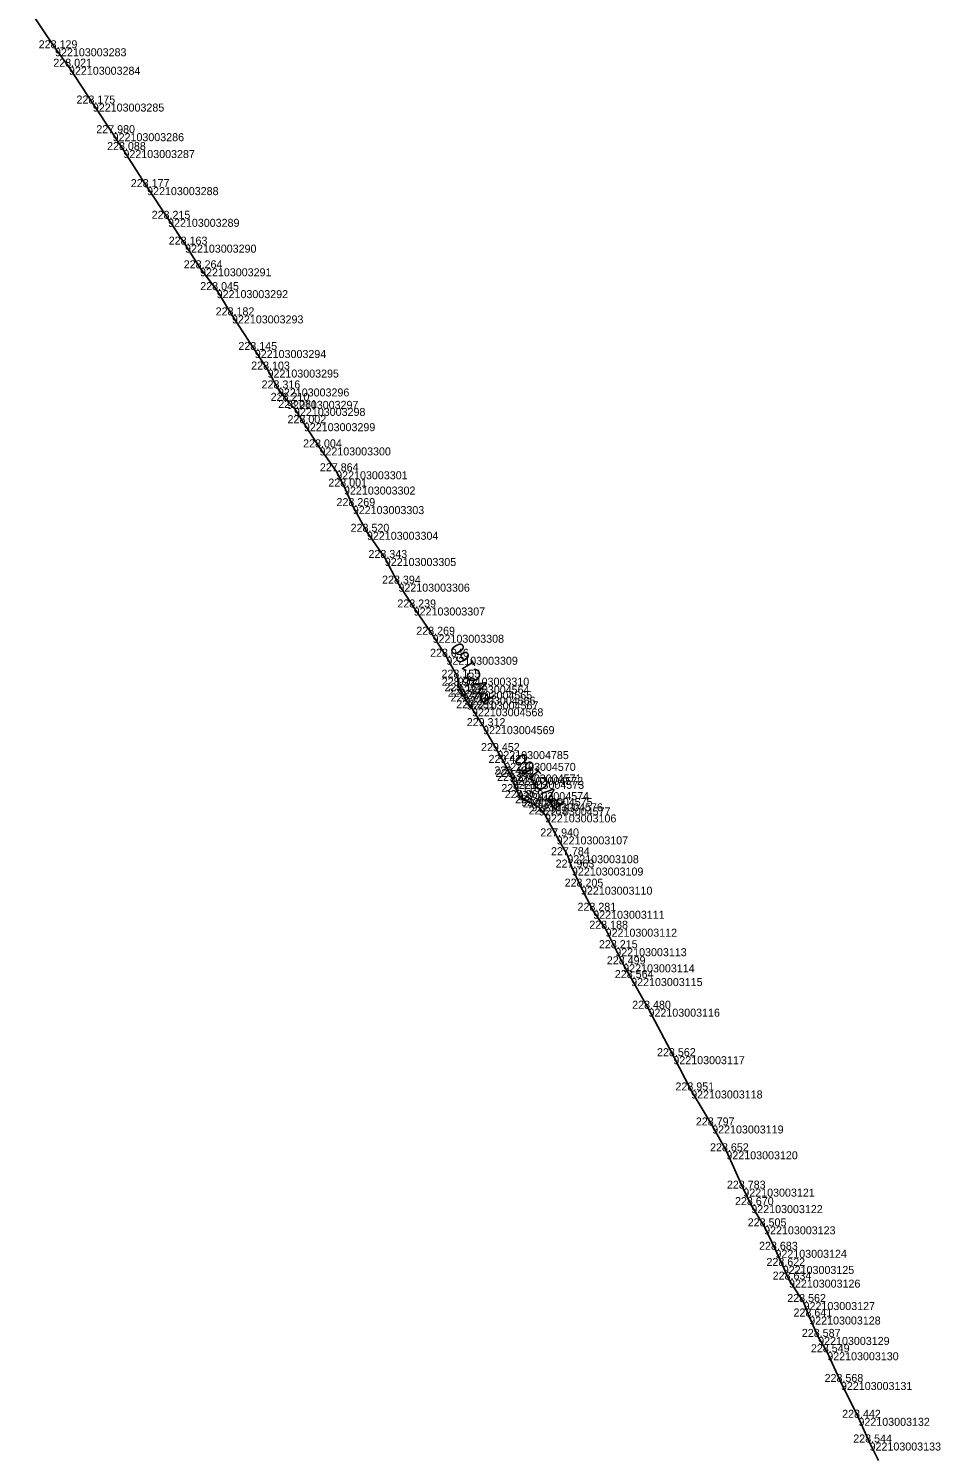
# Model space of a CAD drawing. Extents: x -771047 to -756200, y -1053876 to -1046520.
# Drawn here: x -769310.8 to -769174, y -1050962.3 to -1050749 of the extents above; entities that cross this region are included whole.
import ezdxf

# ---------------------------------------------------------------- set-up
doc = ezdxf.new("R2010")
doc.units = 0
for name, color, linetype in [('Vrstva 32', 7, 'Continuous'), ('Vrstva 33', 7, 'Continuous'), ('Vrstva 60', 7, 'Continuous'), ('Vrstva 61', 7, 'Continuous')]:
    doc.layers.add(name, color=color, linetype=linetype)

msp = doc.modelspace()

# ---------------------------------------------------------------- linework, layer by layer
at = {"layer": 'Vrstva 32'}
for points in [[(-769310.84, -1050745.98), (-769306.85, -1050751.92), (-769304.76, -1050754.69), (-769301.18, -1050760.21), (-769298.21, -1050764.65), (-769296.59, -1050767.18), (-769293.04, -1050772.74), (-769289.9, -1050777.49), (-769287.35, -1050781.36), (-769285.1, -1050784.91), (-769282.61, -1050788.18), (-769280.31, -1050791.97), (-769276.89, -1050797.16), (-769274.98, -1050800.09), (-769273.42, -1050802.92), (-769272.06, -1050804.78), (-769271.01, -1050805.84), (-769269.53, -1050808.13), (-769267.19, -1050811.76), (-769264.68, -1050815.34), (-769263.51, -1050817.63), (-769262.19, -1050820.56), (-769260.07, -1050824.41), (-769257.39, -1050828.34), (-769255.35, -1050832.19), (-769253.06, -1050835.76), (-769250.22, -1050839.85), (-769248.15, -1050843.15), (-769246.44, -1050846.28)], [(-769246.44, -1050846.28), (-769246.4, -1050847.49), (-769246, -1050848.32), (-769245.49, -1050849.14)], [(-769245.49, -1050849.14), (-769245.07, -1050849.85), (-769244.32, -1050850.87), (-769242.65, -1050853.55), (-769240.51, -1050857.29), (-769239.47, -1050859.06), (-769238.61, -1050860.79), (-769238.35, -1050861.17)], [(-769238.35, -1050861.17), (-769238.2, -1050861.75), (-769237.47, -1050863.44), (-769236.94, -1050864.34), (-769235.39, -1050865.11), (-769234.25, -1050865.74), (-769233.37, -1050866.78)], [(-769233.37, -1050866.78), (-769231.61, -1050870.08), (-769230.01, -1050872.9), (-769229.32, -1050874.75), (-769227.97, -1050877.62), (-769226.13, -1050881.23), (-769224.27, -1050883.92), (-769222.82, -1050886.84), (-769221.63, -1050889.26), (-769220.44, -1050891.32), (-769217.84, -1050895.92), (-769214.11, -1050903.03), (-769211.44, -1050908.17), (-769208.29, -1050913.42), (-769206.16, -1050917.29), (-769203.62, -1050922.89), (-769202.42, -1050925.36), (-769200.5, -1050928.54), (-769198.8, -1050932.06), (-769197.7, -1050934.48), (-769196.77, -1050936.53), (-769194.58, -1050939.89), (-769193.73, -1050942.06), (-769192.39, -1050945.12), (-769191.03, -1050947.42), (-769188.98, -1050951.88), (-769186.35, -1050957.25), (-769184.68, -1050960.95), (-769183.32, -1050963.66)]]:
    msp.add_lwpolyline(points, dxfattribs=at)
at = {"layer": 'Vrstva 33'}
for points in [[(-769246.44, -1050846.28), (-769246.4, -1050847.49), (-769246, -1050848.32), (-769245.49, -1050849.14)], [(-769238.35, -1050861.17), (-769238.2, -1050861.75), (-769237.47, -1050863.44), (-769236.94, -1050864.34), (-769235.39, -1050865.11), (-769234.25, -1050865.74), (-769233.37, -1050866.78)]]:
    msp.add_lwpolyline(points, dxfattribs=at)
at = {"layer": 'Vrstva 60'}
for p, q in [((-769306.85, -1050751.92), (-769306.85, -1050751.92)), ((-769304.76, -1050754.69), (-769304.76, -1050754.69)), ((-769301.18, -1050760.21), (-769301.18, -1050760.21)), ((-769298.21, -1050764.65), (-769298.21, -1050764.65)), ((-769296.59, -1050767.18), (-769296.59, -1050767.18)), ((-769293.04, -1050772.74), (-769293.04, -1050772.74)), ((-769289.9, -1050777.49), (-769289.9, -1050777.49)), ((-769287.35, -1050781.36), (-769287.35, -1050781.36)), ((-769285.1, -1050784.91), (-769285.1, -1050784.91)), ((-769282.61, -1050788.18), (-769282.61, -1050788.18)), ((-769280.31, -1050791.97), (-769280.31, -1050791.97)), ((-769276.89, -1050797.16), (-769276.89, -1050797.16)), ((-769274.98, -1050800.09), (-769274.98, -1050800.09)), ((-769273.42, -1050802.92), (-769273.42, -1050802.92)), ((-769272.06, -1050804.78), (-769272.06, -1050804.78)), ((-769271.01, -1050805.84), (-769271.01, -1050805.84)), ((-769269.53, -1050808.13), (-769269.53, -1050808.13)), ((-769267.19, -1050811.76), (-769267.19, -1050811.76)), ((-769264.68, -1050815.34), (-769264.68, -1050815.34)), ((-769263.51, -1050817.63), (-769263.51, -1050817.63)), ((-769262.19, -1050820.56), (-769262.19, -1050820.56)), ((-769260.07, -1050824.41), (-769260.07, -1050824.41)), ((-769257.39, -1050828.34), (-769257.39, -1050828.34)), ((-769255.35, -1050832.19), (-769255.35, -1050832.19)), ((-769253.06, -1050835.76), (-769253.06, -1050835.76)), ((-769250.22, -1050839.85), (-769250.22, -1050839.85)), ((-769248.15, -1050843.15), (-769248.15, -1050843.15)), ((-769246.44, -1050846.28), (-769246.44, -1050846.28)), ((-769246.4, -1050847.49), (-769246.4, -1050847.49)), ((-769246, -1050848.32), (-769246, -1050848.32)), ((-769245.49, -1050849.14), (-769245.49, -1050849.14)), ((-769245.07, -1050849.85), (-769245.07, -1050849.85)), ((-769244.32, -1050850.87), (-769244.32, -1050850.87)), ((-769242.65, -1050853.55), (-769242.65, -1050853.55)), ((-769240.51, -1050857.29), (-769240.51, -1050857.29)), ((-769239.47, -1050859.06), (-769239.47, -1050859.06)), ((-769238.61, -1050860.79), (-769238.61, -1050860.79)), ((-769238.35, -1050861.17), (-769238.35, -1050861.17)), ((-769238.2, -1050861.75), (-769238.2, -1050861.75)), ((-769237.47, -1050863.44), (-769237.47, -1050863.44)), ((-769236.94, -1050864.34), (-769236.94, -1050864.34)), ((-769235.39, -1050865.11), (-769235.39, -1050865.11)), ((-769234.25, -1050865.74), (-769234.25, -1050865.74)), ((-769233.37, -1050866.78), (-769233.37, -1050866.78)), ((-769231.61, -1050870.08), (-769231.61, -1050870.08)), ((-769230.01, -1050872.9), (-769230.01, -1050872.9)), ((-769229.32, -1050874.75), (-769229.32, -1050874.75)), ((-769227.97, -1050877.62), (-769227.97, -1050877.62)), ((-769226.13, -1050881.23), (-769226.13, -1050881.23)), ((-769224.27, -1050883.92), (-769224.27, -1050883.92)), ((-769222.82, -1050886.84), (-769222.82, -1050886.84)), ((-769221.63, -1050889.26), (-769221.63, -1050889.26)), ((-769220.44, -1050891.32), (-769220.44, -1050891.32)), ((-769217.84, -1050895.92), (-769217.84, -1050895.92)), ((-769214.11, -1050903.03), (-769214.11, -1050903.03)), ((-769211.44, -1050908.17), (-769211.44, -1050908.17)), ((-769208.29, -1050913.42), (-769208.29, -1050913.42)), ((-769206.16, -1050917.29), (-769206.16, -1050917.29)), ((-769203.62, -1050922.89), (-769203.62, -1050922.89)), ((-769202.42, -1050925.36), (-769202.42, -1050925.36)), ((-769200.5, -1050928.54), (-769200.5, -1050928.54)), ((-769198.8, -1050932.06), (-769198.8, -1050932.06)), ((-769197.7, -1050934.48), (-769197.7, -1050934.48)), ((-769196.77, -1050936.53), (-769196.77, -1050936.53)), ((-769194.58, -1050939.89), (-769194.58, -1050939.89)), ((-769193.73, -1050942.06), (-769193.73, -1050942.06)), ((-769192.39, -1050945.12), (-769192.39, -1050945.12)), ((-769191.03, -1050947.42), (-769191.03, -1050947.42)), ((-769188.98, -1050951.88), (-769188.98, -1050951.88)), ((-769186.35, -1050957.25), (-769186.35, -1050957.25)), ((-769184.68, -1050960.95), (-769184.68, -1050960.95))]:
    msp.add_line(p, q, dxfattribs=at)

# ---------------------------------------------------------------- texts
at = {"layer": 'Vrstva 33'}
for rotation, p in [(121.4913, (-769240.81, -1050849.29)), (129.9401, (-769230.24, -1050865.02))]:
    msp.add_text('PVC160', height=2, rotation=rotation, dxfattribs=at).set_placement(p)
at = {"layer": 'Vrstva 60'}
for s, p in [('922103003283', (-769306.85, -1050753.12)), ('922103003284', (-769304.76, -1050755.89)), ('922103003285', (-769301.18, -1050761.41)), ('922103003286', (-769298.21, -1050765.85)), ('922103003287', (-769296.59, -1050768.38)), ('922103003288', (-769293.04, -1050773.94)), ('922103003289', (-769289.9, -1050778.69)), ('922103003290', (-769287.35, -1050782.56)), ('922103003291', (-769285.1, -1050786.11)), ('922103003292', (-769282.61, -1050789.38)), ('922103003293', (-769280.31, -1050793.17)), ('922103003294', (-769276.89, -1050798.36)), ('922103003295', (-769274.98, -1050801.29)), ('922103003296', (-769273.42, -1050804.12)), ('922103003297', (-769272.06, -1050805.98)), ('922103003298', (-769271.01, -1050807.04)), ('922103003299', (-769269.53, -1050809.33)), ('922103003300', (-769267.19, -1050812.96)), ('922103003301', (-769264.68, -1050816.54)), ('922103003302', (-769263.51, -1050818.83)), ('922103003303', (-769262.19, -1050821.76)), ('922103003304', (-769260.07, -1050825.61)), ('922103003305', (-769257.39, -1050829.54)), ('922103003306', (-769255.35, -1050833.39)), ('922103003307', (-769253.06, -1050836.96)), ('922103003308', (-769250.22, -1050841.05)), ('922103003309', (-769248.15, -1050844.35)), ('922103003310', (-769246.44, -1050847.48)), ('922103004564', (-769246.4, -1050848.69)), ('922103004565', (-769246, -1050849.52)), ('922103004566', (-769245.49, -1050850.34)), ('922103004567', (-769245.07, -1050851.05)), ('922103004568', (-769244.32, -1050852.07)), ('922103004569', (-769242.65, -1050854.75)), ('922103004785', (-769240.51, -1050858.49)), ('922103004570', (-769239.47, -1050860.26)), ('922103004571', (-769238.61, -1050861.99)), ('922103004572', (-769238.35, -1050862.37)), ('922103004573', (-769238.2, -1050862.95)), ('922103004574', (-769237.47, -1050864.64)), ('922103004575', (-769236.94, -1050865.54)), ('922103004576', (-769235.39, -1050866.31)), ('922103004577', (-769234.25, -1050866.94)), ('922103003106', (-769233.37, -1050867.98)), ('922103003107', (-769231.61, -1050871.28)), ('922103003108', (-769230.01, -1050874.1)), ('922103003109', (-769229.32, -1050875.95)), ('922103003110', (-769227.97, -1050878.82)), ('922103003111', (-769226.13, -1050882.43)), ('922103003112', (-769224.27, -1050885.12)), ('922103003113', (-769222.82, -1050888.04)), ('922103003114', (-769221.63, -1050890.46)), ('922103003115', (-769220.44, -1050892.52)), ('922103003116', (-769217.84, -1050897.11)), ('922103003117', (-769214.11, -1050904.23)), ('922103003118', (-769211.44, -1050909.37)), ('922103003119', (-769208.29, -1050914.62)), ('922103003120', (-769206.16, -1050918.49)), ('922103003121', (-769203.62, -1050924.09)), ('922103003122', (-769202.42, -1050926.56)), ('922103003123', (-769200.5, -1050929.74)), ('922103003124', (-769198.8, -1050933.26)), ('922103003125', (-769197.7, -1050935.68)), ('922103003126', (-769196.77, -1050937.73)), ('922103003127', (-769194.58, -1050941.09)), ('922103003128', (-769193.73, -1050943.26)), ('922103003129', (-769192.39, -1050946.32)), ('922103003130', (-769191.03, -1050948.62)), ('922103003131', (-769188.98, -1050953.08)), ('922103003132', (-769186.35, -1050958.45)), ('922103003133', (-769184.68, -1050962.15))]:
    msp.add_text(s, height=1.2, dxfattribs=at).set_placement(p)
at = {"layer": 'Vrstva 61'}
for s, p in [('228.129', (-769309.3, -1050751.92)), ('228.021', (-769307.11, -1050754.69)), ('228.175', (-769303.63, -1050760.21)), ('227.980', (-769300.66, -1050764.65)), ('228.088', (-769299.04, -1050767.18)), ('228.177', (-769295.49, -1050772.74)), ('228.215', (-769292.36, -1050777.49)), ('228.163', (-769289.8, -1050781.36)), ('228.264', (-769287.55, -1050784.91)), ('228.045', (-769285.07, -1050788.18)), ('228.182', (-769282.76, -1050791.97)), ('228.145', (-769279.35, -1050797.16)), ('228.103', (-769277.43, -1050800.09)), ('228.316', (-769275.87, -1050802.92)), ('228.210', (-769274.51, -1050804.78)), ('228.081', (-769273.37, -1050805.84)), ('228.002', (-769271.98, -1050808.13)), ('228.004', (-769269.64, -1050811.76)), ('227.864', (-769267.13, -1050815.34)), ('228.001', (-769265.86, -1050817.63)), ('228.269', (-769264.64, -1050820.56)), ('228.520', (-769262.52, -1050824.41)), ('228.343', (-769259.84, -1050828.34)), ('228.394', (-769257.8, -1050832.19)), ('228.239', (-769255.51, -1050835.76)), ('228.269', (-769252.67, -1050839.85)), ('228.046', (-769250.6, -1050843.15)), ('228.155', (-769248.89, -1050846.28)), ('228.904', (-769248.85, -1050847.49)), ('229.167', (-769248.45, -1050848.32)), ('229.297', (-769247.94, -1050849.14)), ('229.274', (-769247.52, -1050849.85)), ('229.251', (-769246.68, -1050850.87)), ('229.312', (-769245.1, -1050853.55)), ('229.452', (-769242.96, -1050857.29)), ('229.421', (-769241.83, -1050859.06)), ('229.401', (-769240.96, -1050860.79)), ('229.392', (-769240.8, -1050861.17)), ('229.271', (-769240.55, -1050861.75)), ('229.116', (-769239.92, -1050863.44)), ('228.869', (-769239.4, -1050864.34)), ('228.448', (-769237.85, -1050865.11)), ('228.296', (-769236.7, -1050865.74)), ('227.783', (-769235.82, -1050866.78)), ('227.940', (-769234.07, -1050870.08)), ('227.784', (-769232.46, -1050872.9)), ('227.963', (-769231.77, -1050874.75)), ('228.205', (-769230.42, -1050877.62)), ('228.281', (-769228.49, -1050881.23)), ('228.188', (-769226.72, -1050883.92)), ('228.215', (-769225.27, -1050886.84)), ('228.499', (-769224.09, -1050889.26)), ('228.564', (-769222.89, -1050891.32)), ('228.480', (-769220.29, -1050895.92)), ('228.562', (-769216.56, -1050903.03)), ('228.951', (-769213.8, -1050908.17)), ('228.797', (-769210.74, -1050913.42)), ('228.652', (-769208.61, -1050917.29)), ('228.783', (-769206.08, -1050922.89)), ('228.670', (-769204.87, -1050925.36)), ('228.505', (-769202.96, -1050928.54)), ('228.683', (-769201.26, -1050932.06)), ('228.622', (-769200.15, -1050934.48)), ('228.634', (-769199.22, -1050936.53)), ('228.562', (-769197.03, -1050939.89)), ('228.641', (-769196.09, -1050942.06)), ('228.587', (-769194.84, -1050945.12)), ('228.549', (-769193.48, -1050947.42)), ('228.568', (-769191.43, -1050951.88)), ('228.442', (-769188.8, -1050957.25)), ('228.544', (-769187.13, -1050960.95))]:
    msp.add_text(s, height=1.2, dxfattribs=at).set_placement(p)

doc.saveas('drawing.dxf')
